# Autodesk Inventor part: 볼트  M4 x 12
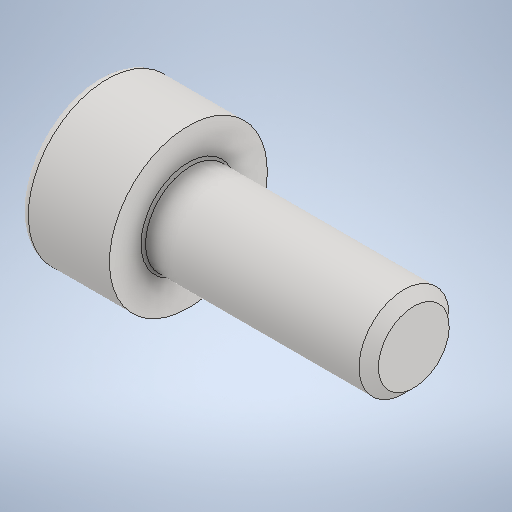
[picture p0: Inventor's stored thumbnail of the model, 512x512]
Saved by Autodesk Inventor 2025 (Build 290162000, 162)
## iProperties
Created: 2024-08
Part Number: 볼트  M4 x 12
Material: 스테인리스강
Description: 6각머리 태핑 나사
Document SubType Name: Modeling
Designer: deana
Density: 8.08 g/cm^3
Appearance: 기본값
Author: jhkim
Sending System: Autodesk Inventor 2025
Preprocessor: ST-DEVELOPER v20
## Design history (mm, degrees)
feature "Solid1"
node "솔리드1"
